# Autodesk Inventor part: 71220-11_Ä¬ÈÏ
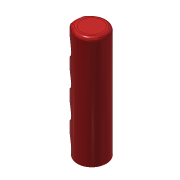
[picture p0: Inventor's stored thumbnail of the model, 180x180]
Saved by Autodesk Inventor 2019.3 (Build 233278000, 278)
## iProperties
Created: 2010-06
Part Number: 71220-11_Ä¬ÈÏ
Material: Ogólny
Document SubType Name: Modeling
Designer: CADENGINEERING4
Density: 1 g/cm^3
Appearance: Jasnoczerwona
Author: CADENGINEERING4
Revision Number: ÈÎºÎ
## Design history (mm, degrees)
feature "NONE"
node "Bryła1"
